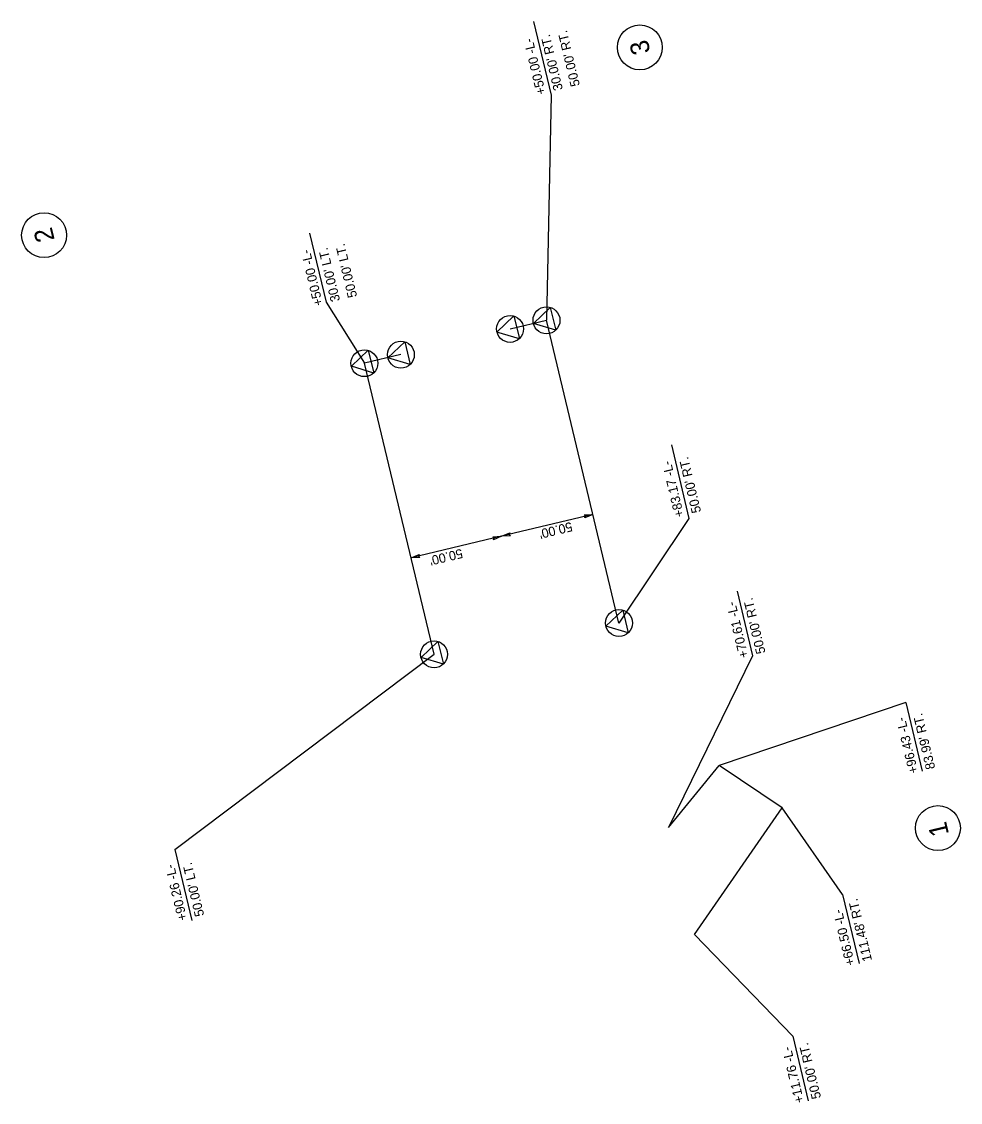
# Model space of a CAD drawing. Extents: x 1735947 to 1736449, y 700225 to 700803.
import ezdxf

# ---------------------------------------------------------------- set-up
doc = ezdxf.new("R2010")
doc.units = 0
for name, color, linetype in [('Prop Easement Construction', 7, 'Continuous'), ('Prop Easement Construction Station Offsets', 7, 'Continuous'), ('Prop Parcel Number CELL', 7, 'Continuous'), ('Prop Parcel Number Text', 7, 'Continuous'), ('Prop ROW Marker CELL', 7, 'Continuous'), ('Prop ROW RW Lines', 7, 'Continuous'), ('Prop ROW Station Offsets', 7, 'Continuous')]:
    doc.layers.add(name, color=color, linetype=linetype)

msp = doc.modelspace()

# ---------------------------------------------------------------- linework, layer by layer
at = {"layer": 'Prop Easement Construction'}
for p, q in [((1736293.29, 700372.44), (1736320.23, 700405.55)), ((1736354, 700382.95), (1736320.23, 700405.55)), ((1736307.19, 700315.24), (1736354, 700382.95))]:
    msp.add_line(p, q, dxfattribs=at)
at = {"layer": 'Prop Easement Construction Station Offsets'}
for p, q in [((1736329.89, 700498.83), (1736338.13, 700464.27)), ((1736420.07, 700439.39), (1736428.86, 700402.5)), ((1736386.3, 700336.65), (1736395.09, 700299.76)), ((1736359.61, 700260.8), (1736367.84, 700226.25))]:
    msp.add_line(p, q, dxfattribs=at)
for points in [[(1736338.13, 700464.27), (1736293.29, 700372.44)], [(1736420.07, 700439.39), (1736320.23, 700405.55)], [(1736386.3, 700336.65), (1736354, 700382.95)], [(1736359.61, 700260.8), (1736307.19, 700315.24)]]:
    msp.add_lwpolyline(points, dxfattribs=at)
at = {"layer": 'Prop Parcel Number CELL'}
for p, q in [((1736277.87, 700789.71), (1736277.87, 700789.71)), ((1735959.33, 700689.25), (1735959.33, 700689.25)), ((1736437.27, 700372.14), (1736437.27, 700372.14))]:
    msp.add_line(p, q, dxfattribs=at)
for centre in [(1736277.87, 700789.71), (1735959.33, 700689.25), (1736437.27, 700372.14)]:
    msp.add_circle(centre, 12, dxfattribs=at)
at = {"layer": 'Prop ROW Marker CELL'}
for p, q in [((1736227.96, 700643.73), (1736227.96, 700643.73)), ((1736208.5, 700639.14), (1736208.5, 700639.14)), ((1736130.63, 700620.79), (1736130.63, 700620.79)), ((1736150.1, 700625.37), (1736150.1, 700625.37)), ((1736266.73, 700481.81), (1736266.73, 700481.81)), ((1736167.88, 700465.1), (1736167.88, 700465.1))]:
    msp.add_line(p, q, dxfattribs=at)
for points in [[(1736232.92, 700638.48), (1736220.96, 700642.06), (1736230.02, 700650.64)], [(1736213.45, 700633.89), (1736201.49, 700637.47), (1736210.55, 700646.05)], [(1736155.05, 700620.13), (1736143.09, 700623.71), (1736152.15, 700632.29)], [(1736135.58, 700615.54), (1736123.63, 700619.12), (1736132.68, 700627.7)], [(1736271.68, 700476.57), (1736259.72, 700480.15), (1736268.78, 700488.73)], [(1736172.83, 700459.86), (1736160.88, 700463.43), (1736169.93, 700472.02)]]:
    msp.add_lwpolyline(points, close=True, dxfattribs=at)
for centre in [(1736227.96, 700643.73), (1736208.5, 700639.14), (1736150.1, 700625.37), (1736130.63, 700620.79), (1736266.73, 700481.81), (1736167.88, 700465.1)]:
    msp.add_circle(centre, 7.2, dxfattribs=at)
at = {"layer": 'Prop ROW RW Lines'}
for p, q in [((1736208.5, 700639.14), (1736227.96, 700643.73)), ((1736266.73, 700481.81), (1736227.96, 700643.73)), ((1736150.1, 700625.37), (1736130.63, 700620.79)), ((1736167.88, 700465.1), (1736130.63, 700620.79))]:
    msp.add_line(p, q, dxfattribs=at)
at = {"layer": 'Prop ROW Station Offsets'}
for p, q in [((1736221.02, 700803.48), (1736230.41, 700764.09)), ((1736230.41, 700764.09), (1736227.96, 700643.73)), ((1736101.31, 700690.33), (1736110.12, 700653.39)), ((1736110.12, 700653.39), (1736130.63, 700620.79)), ((1736294.76, 700577.05), (1736304.16, 700537.64)), ((1736252.82, 700539.9), (1736203.96, 700528.21)), ((1736203.96, 700528.21), (1736155.55, 700516.62)), ((1736029.27, 700360.76), (1736038.35, 700322.69))]:
    msp.add_line(p, q, dxfattribs=at)
for points in [[(1736248.07, 700539.6), (1736252.82, 700539.9), (1736248.43, 700538), (1736248.82, 700538.95)], [(1736199.21, 700527.9), (1736203.96, 700528.21), (1736199.57, 700526.3), (1736199.96, 700527.25)], [(1736208.71, 700528.51), (1736203.96, 700528.21), (1736208.35, 700530.11), (1736207.96, 700529.17)], [(1736160.3, 700516.92), (1736155.55, 700516.62), (1736159.94, 700518.53), (1736159.55, 700517.58)]]:
    msp.add_lwpolyline(points, close=True, dxfattribs=at)
for points in [[(1736304.16, 700537.64), (1736266.73, 700481.81)], [(1736029.27, 700360.76), (1736167.88, 700465.1)]]:
    msp.add_lwpolyline(points, dxfattribs=at)

# ---------------------------------------------------------------- texts
at = {"layer": 'Prop Easement Construction Station Offsets'}
for s, p in [("50.00' RT.", (1736345.12, 700465.94)), ('+70.61 -L-', (1736336, 700463.76)), ('+96.43 -L-', (1736426.74, 700401.99)), ("83.99' RT.", (1736435.86, 700404.17)), ("111.48' RT.", (1736402.08, 700301.43)), ('+66.50 -L-', (1736392.96, 700299.25)), ("50.00' RT.", (1736374.83, 700227.91)), ('+11.76 -L-', (1736365.72, 700225.74))]:
    msp.add_text(s, height=5, rotation=103.40592, dxfattribs=at).set_placement(p)
at = {"layer": 'Prop Parcel Number Text'}
for s, p in [('3', (1736283.62, 700787.13)), ('2', (1735965.05, 700686.81)), ('1', (1736443.24, 700368.95))]:
    msp.add_text(s, height=10, rotation=103.40592, dxfattribs=at).set_placement(p)
at = {"layer": 'Prop ROW Station Offsets'}
for s, rotation, p in [('+50.00 -L-', 103.40592, (1736227.65, 700765.05)), ("30.00' RT.", 103.40592, (1736236.77, 700767.22)), ("50.00' RT.", 103.40592, (1736245.89, 700769.4)), ("50.00' LT.", 103.40592, (1736126.76, 700656.46)), ('+50.00 -L-', 103.40592, (1736108.52, 700652.11)), ("30.00' LT.", 103.40592, (1736117.64, 700654.29)), ("50.00' RT.", 103.40592, (1736310.68, 700541.26)), ('+83.17 -L-', 103.40592, (1736301.56, 700539.09)), ("50.00'", 193.65186, (1736241.12, 700535.93)), ("50.00'", 193.65186, (1736182.48, 700521.63)), ('+90.26 -L-', 103.40592, (1736035.89, 700323.29)), ("50.00' LT.", 103.40592, (1736045.01, 700325.46))]:
    msp.add_text(s, height=5, rotation=rotation, dxfattribs=at).set_placement(p)

doc.saveas('drawing.dxf')
